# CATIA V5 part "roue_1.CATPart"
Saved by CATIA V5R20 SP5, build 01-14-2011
Part number: roue_1
Publications: "diamètre pivot en B", "diamètre pivot en A"
Bounding box of the stored display mesh (mm): x 0 to 12, y -45 to 9, z 43.197 to 96.803
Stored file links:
  M:\EU_thinkMotion\IAO_2010\iao\IAO_MMS_Groupe2\IAO_MMS_Groupe2\sdubois\sdubois\sdubois\IAO_mecanisme\roue_1.CATPart
  M:\EU_thinkMotion\IAO_2010\iao\IAO_MMS_Groupe2\IAO_MMS_Groupe2\sdubois\sdubois\sdubois\IAO_mecanisme\assembage final.CATProduct
  M:\EU_thinkMotion\IAO_2010\iao\IAO_MMS_Groupe2\IAO_MMS_Groupe2\sdubois\sdubois\sdubois\IAO_mecanisme\squelette_1.CATPart
  M:\EU_thinkMotion\IAO_2010\iao\IAO_MMS_Groupe2\IAO_MMS_Groupe2\sdubois\sdubois\sdubois\IAO_mecanisme\bati_0.CATPart
  M:\EU_thinkMotion\IAO_2010\iao\IAO_MMS_Groupe2\IAO_MMS_Groupe2\sdubois\sdubois\sdubois\IAO_mecanisme\barre_6.CATPart
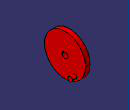
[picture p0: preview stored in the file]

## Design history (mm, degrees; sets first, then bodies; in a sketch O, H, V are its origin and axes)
Parameters
  `diamètre pivot en B` = 6 mm
  `diamètre pivot en A` = 8 mm
External parameters (linked from other documents)
  External.largeur_barre = 6 mm
Set1
  Point1 to Point3: linked copy from another document
  Line1: linked copy from another document
  DatumSurface1: linked copy from another document
Body1 (main body)
  Sketch1 on yz-plane, origin (0, 0, 0), H (0, 1, 0), V (0, 0, 1)
    circle A1 centre (-18, 70) radius 27
    point P1 (-18, 70)
    circle A2 centre (-18, 70) radius 4
    point P2 (-18, 70)
    reference projected point E1 (-18, 70) from Point1
    reference projected point E2 (-18, 70) from Point1
    reference projected point E3 (-2.3441, 48.0025) from Point3
    radius A2 = 4 {= `diamètre pivot en A` /2}
    distance P2 E1 = 0
    distance P1 E2 = 0
    distance A1 E3 = 0
  Pad1: profile Sketch1, direction (1, 0, 0), length 6 {= External.largeur_barre}, opposite side up to face of DatumSurface1
  Sketch2 on end face of Pad1, origin (6, 0, 0), H (0, 1, 0), V (0, 0, 1)
    circle A1 centre (-5.2433, 52.0761) radius 3
    point P1 (-5.2433, 52.0761)
    reference projected point E1 (-5.2433, 52.0761) from Line1
    distance P1 E1 = 0
    radius A1 = 3 {= `diamètre pivot en B` /2}
  Pad2: profile Sketch2, direction (1, 0, 0), length 6 {= External.largeur_barre}, opposite side up to end face of Pad1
